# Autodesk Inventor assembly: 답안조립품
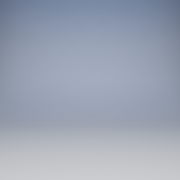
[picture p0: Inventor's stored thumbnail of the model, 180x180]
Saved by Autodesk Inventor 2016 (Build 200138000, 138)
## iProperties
Created: 2018-07
Part Number: 답안조립품
Document SubType Name: Assembly
Designer: 2-PC11
Author: 2-PC11
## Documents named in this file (1)
- C:\Users\2-PC11\Desktop\갈매기\480708V1014\답안조립품.iam
